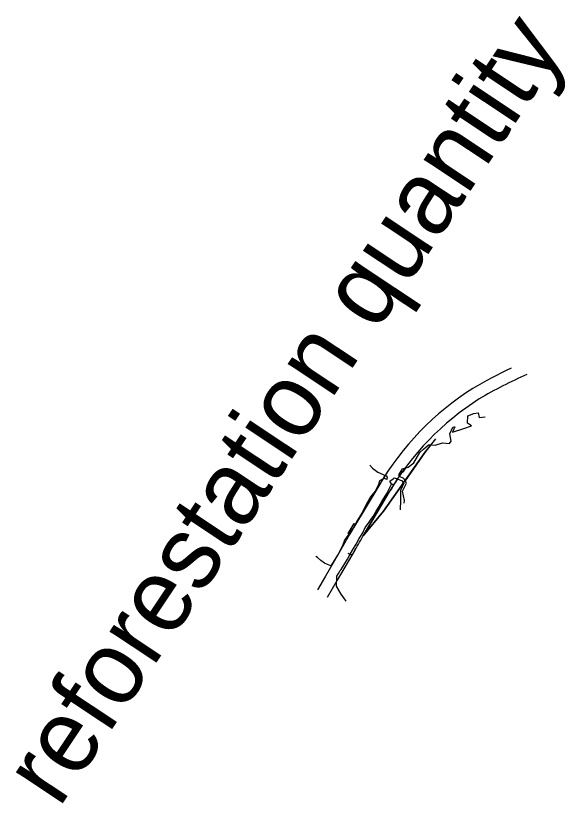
# Model space of a CAD drawing. Extents: x 2357856 to 2382083, y 331121 to 347536.
# Drawn here: x 2357856 to 2362351, y 341091 to 347536 of the extents above; entities that cross this region are included whole.
import ezdxf

# ---------------------------------------------------------------- set-up
doc = ezdxf.new("R2010")
doc.units = 0
for name, color, linetype in [('Blank Plan Sheet Both CELL', 7, 'Continuous'), ('Old_Level_1', 7, 'Continuous'), ('Old_Level_18', 7, 'Continuous'), ('Old_Level_38', 7, 'Continuous'), ('Stabilization Guidelines Sheet for Maintenance CELL', 7, 'Continuous')]:
    doc.layers.add(name, color=color, linetype=linetype)

msp = doc.modelspace()

# ---------------------------------------------------------------- linework, layer by layer
at = {"layer": 'Blank Plan Sheet Both CELL'}
msp.add_line((2360573.5, 343138.8), (2360604.5, 343120.5), dxfattribs=at)
for points in [[(2361019, 343804.9), (2361020.3, 343804.6), (2361021.9, 343804.4), (2361024.2, 343804.6), (2361025.9, 343805.1), (2361027.6, 343805.9), (2361029.5, 343807.4), (2361030.8, 343809.2), (2361033.6, 343813.4), (2361044.4, 343830.1), (2361047.5, 343835.7), (2361064.6, 343840.2), (2361113.4, 343876.5), (2361161.2, 343960.3), (2361191.6, 343989.1), (2361232.8, 344023.9), (2361251.2, 344023.1), (2361201.9, 343960.4), (2361040.2, 343730.9), (2361029.9, 343748.1), (2360999.4, 343762.6), (2360995, 343770.6)], [(2360877.8, 343774.9), (2360886.3, 343771.1), (2360894.9, 343760.1), (2360891.7, 343740.4), (2360875.3, 343749.9), (2360858.7, 343744.4), (2360858.2, 343744.2)], [(2360995, 343770.6), (2360990, 343779.3), (2361007.9, 343808.9), (2361018.9, 343805), (2361019, 343804.9)], [(2360977.8, 343745.1), (2360981.1, 343744.2), (2361010.1, 343731.2), (2361027.8, 343713.3), (2360863.6, 343480.3), (2360697.5, 343279.5)], [(2360911.3, 343638.8), (2360914, 343642.3), (2360920.1, 343650.2), (2360928.7, 343662.4), (2360937.4, 343674.5), (2360943.9, 343685), (2360945, 343687.6), (2360945.4, 343689.6), (2360945.2, 343692), (2360944.6, 343693.7), (2360944.6, 343693.7)], [(2360944.6, 343693.7), (2360943.4, 343696.3), (2360941.9, 343697.9), (2360940.2, 343699), (2360938.4, 343699.8), (2360929, 343702.8), (2360929.5, 343704.8), (2360925.2, 343714.3), (2360916.5, 343727.6), (2360941.9, 343746.8), (2360950.6, 343752.9), (2360977.8, 343745.1)], [(2360629.4, 343162.9), (2360604.5, 343120.5), (2360590.8, 343128.6), (2360591.2, 343129.4), (2360610.1, 343162.7), (2360639.2, 343212.3), (2360663.7, 343256.4), (2360669.8, 343265.4), (2360695, 343303.9), (2360714.7, 343346.7), (2360740.8, 343382.3), (2360768.9, 343423), (2360779.8, 343439), (2360805.3, 343481.1), (2360818.3, 343503.3), (2360827.2, 343519.4), (2360830.9, 343518.5), (2360838.9, 343531.1), (2360841.4, 343535.3), (2360843.9, 343539.6), (2360854.5, 343556.5), (2360862.9, 343568.8), (2360868.2, 343577.3), (2360882, 343597.9), (2360896.5, 343618.1), (2360905.1, 343630.3), (2360908, 343634.3), (2360911, 343638.3), (2360911.3, 343638.8)], [(2360705.5, 343293.4), (2360911.1, 343638.5), (2360911.2, 343638.6)], [(2360911.2, 343638.6), (2360911.1, 343638.5), (2360705.5, 343293.4)]]:
    msp.add_lwpolyline(points, dxfattribs=at)
msp.add_lwpolyline([(2360575.7, 343298.7), (2360623.9, 343380.8), (2360633.1, 343375.3), (2360624.1, 343357), (2360586.6, 343301.3), (2360582, 343295)], close=True, dxfattribs=at)
for centre, radius, start, end in [((2362851.6, 342499.6), 2350, 147.13245, 148.02007), ((2362851.6, 342499.6), 2250, 144.53733, 145.60565), ((2362851.6, 342499.6), 2250, 144.53733, 145.60565), ((2362851.6, 342499.6), 2250, 146.38605, 147.94515), ((2362851.6, 342499.6), 2250, 146.38605, 147.94515), ((2362851.6, 342499.6), 2250, 149.58071, 149.58633), ((2362851.6, 342499.6), 2250, 149.58071, 149.58633), ((2355372.4, 346314.7), 6129.4, 329.05546, 330.4675), ((2355372.4, 346314.7), 6129.4, 330.31758, 330.4675)]:
    msp.add_arc(centre, radius, start, end, dxfattribs=at)
at = {"layer": 'Old_Level_1'}
for p, q in [((2361201.9, 343960.4), (2361291, 344073.8)), ((2360863.6, 343480.3), (2361201.9, 343960.4)), ((2360697.5, 343279.5), (2360863.6, 343480.3))]:
    msp.add_line(p, q, dxfattribs=at)
msp.add_lwpolyline([(2360588.9, 343291), (2360575.7, 343298.7), (2360623.9, 343380.8), (2360636.6, 343373.3)], dxfattribs=at)
at = {"layer": 'Old_Level_18'}
for points in [[(2361031.7, 343547.2), (2361035.2, 343569.6), (2361019.6, 343645.6), (2361052.5, 343710.4), (2361029.9, 343748.1), (2360999.4, 343762.6), (2360990, 343779.3), (2361019.7, 343828.4), (2361064.6, 343840.2), (2361113.4, 343876.5), (2361161.2, 343960.3), (2361191.6, 343989.1), (2361232.8, 344023.9), (2361287.4, 344021.8), (2361347.5, 344040.2), (2361404.3, 344034.1), (2361417.1, 344054.9), (2361405.3, 344113.7), (2361430.5, 344169.7), (2361446.4, 344172), (2361427.2, 344129.3), (2361522.2, 344159), (2361584.2, 344179.5), (2361550.4, 344200.4), (2361552.9, 344261.8), (2361602.2, 344281.5), (2361638.3, 344286.9), (2361646.3, 344247.4), (2361696.7, 344252.1)], [(2360752.5, 343856.5), (2360774.2, 343832.1), (2360817.3, 343801.7), (2360886.3, 343771.1), (2360894.9, 343760.1), (2360891.7, 343740.4), (2360875.3, 343749.9), (2360858.7, 343744.4), (2360832.5, 343726.9), (2360820, 343691.6), (2360794.8, 343645.5), (2360758.8, 343598.2), (2360719.7, 343531.2), (2360691.7, 343473.9), (2360645.2, 343399.9), (2360624.1, 343357), (2360586.6, 343301.3), (2360545, 343244.8), (2360528.4, 343198.8), (2360494.4, 343128), (2360434.3, 343034.8), (2360404.6, 343043.5), (2360380.7, 343056.7), (2360351.4, 343077), (2360323, 343102.4), (2360310.9, 343111)], [(2360558.9, 342743.9), (2360540.5, 342772.4), (2360517, 342802.7), (2360479.8, 342867), (2360482, 342948.5), (2360495.8, 342971.6), (2360510.8, 342994.4), (2360517.6, 343004.8), (2360539.2, 343039.2), (2360568.8, 343087.5), (2360591.2, 343129.4), (2360610.1, 343162.7), (2360639.2, 343212.3), (2360663.7, 343256.4), (2360669.8, 343265.4), (2360695, 343303.9), (2360714.7, 343346.7), (2360720.9, 343355.1), (2360724.9, 343360.6), (2360740.8, 343382.3), (2360768.9, 343423), (2360779.8, 343439), (2360805.3, 343481.1), (2360818.3, 343503.3), (2360849.7, 343560), (2360862.7, 343581.5), (2360890.8, 343627.1), (2360900.2, 343642.2), (2360917.8, 343680.2), (2360927.9, 343698), (2360929.5, 343704.8), (2360925.2, 343714.3), (2360916.5, 343727.6), (2360941.9, 343746.8), (2360950.6, 343752.9), (2360981.1, 343744.2), (2361010.1, 343731.2), (2361031.2, 343709.8), (2361002.8, 343651.2), (2361003.6, 343572.3), (2360999.5, 343492.4)]]:
    msp.add_lwpolyline(points, dxfattribs=at)
at = {"layer": 'Old_Level_38'}
for points in [[(2361595.3, 344485.6), (2361594.9, 344485.3), (2361594.4, 344485)], [(2360825.1, 343689.4), (2360619, 343343.7), (2360618.7, 343343.2)], [(2360911.2, 343638.6), (2360911.1, 343638.5), (2360705.5, 343293.4)], [(2360543.5, 343214.1), (2360543.4, 343213.9), (2360388.8, 342950.4), (2360322.9, 342837)], [(2360629.4, 343162.9), (2360485.6, 342917.7), (2360402.2, 342774.5)]]:
    msp.add_lwpolyline(points, dxfattribs=at)
for centre, radius, start, end in [((2363222.4, 341788.3), 3150, 114.65961, 121.09914), ((2363222.4, 341788.3), 3050, 112.85534, 121.08894), ((2362851.6, 342499.6), 2350, 122.34155, 149.58225), ((2362851.6, 342499.6), 2250, 122.35534, 149.58633), ((2355371.9, 346315), 6030, 329.05327, 330.47262), ((2355372.4, 346314.7), 6129.4, 329.05546, 330.4675)]:
    msp.add_arc(centre, radius, start, end, dxfattribs=at)
at = {"layer": 'Stabilization Guidelines Sheet for Maintenance CELL'}
for points in [[(2361007.9, 343808.9), (2361018.9, 343805), (2361020.3, 343804.6), (2361021.9, 343804.4), (2361024.2, 343804.6), (2361025.9, 343805.1), (2361027.6, 343805.9), (2361029.5, 343807.4), (2361030.8, 343809.2), (2361033.6, 343813.4), (2361044.4, 343830.1), (2361047.5, 343835.7)], [(2360827.2, 343519.4), (2360830.9, 343518.5), (2360838.9, 343531.1), (2360841.4, 343535.3), (2360843.9, 343539.6), (2360854.5, 343556.5), (2360862.9, 343568.8), (2360868.2, 343577.3), (2360882, 343597.9), (2360896.5, 343618.1), (2360905.1, 343630.3), (2360908, 343634.3), (2360911, 343638.3), (2360914, 343642.3), (2360920.1, 343650.2), (2360928.7, 343662.4), (2360937.4, 343674.5), (2360943.9, 343685), (2360945, 343687.6), (2360945.4, 343689.6), (2360945.2, 343692), (2360944.6, 343693.7), (2360943.4, 343696.3), (2360941.9, 343697.9), (2360940.2, 343699), (2360938.4, 343699.8), (2360929, 343702.8)]]:
    msp.add_lwpolyline(points, dxfattribs=at)

# ---------------------------------------------------------------- texts
at = {"layer": 'Blank Plan Sheet Both CELL'}
msp.add_text('reforestation quantity', height=600, rotation=56.36098, dxfattribs=at).set_placement((2358209.6, 341044.2))

doc.saveas('drawing.dxf')
